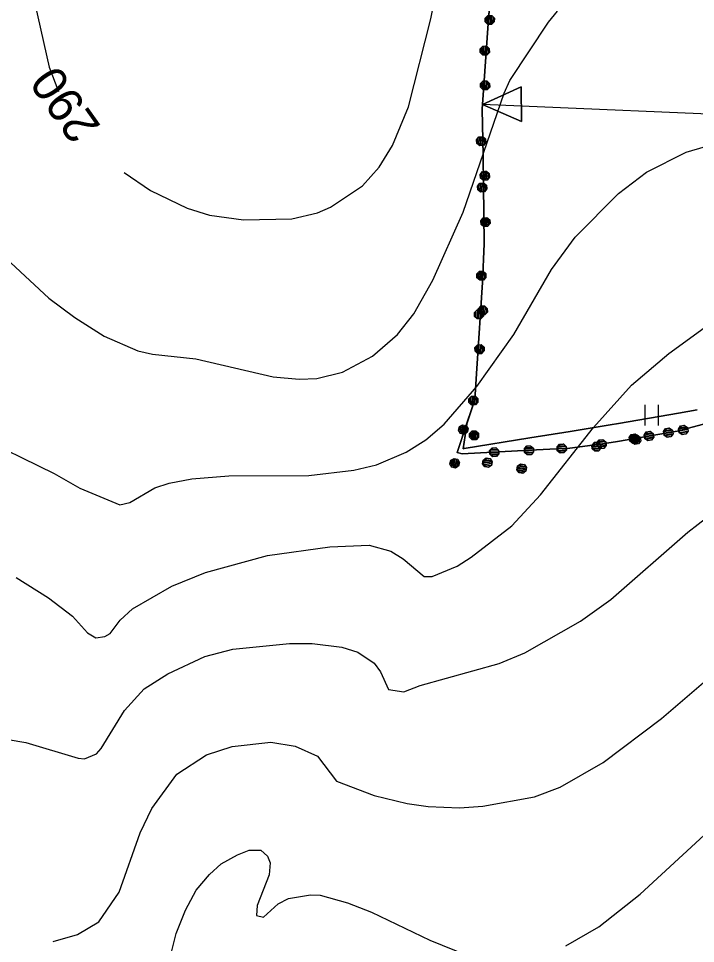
# Model space of a CAD drawing. Extents: x -645676 to -642474, y -1077513 to -1072613.
# Drawn here: x -644532.5 to -644289.3, y -1077150 to -1076817.6 of the extents above; entities that cross this region are included whole.
import ezdxf

# ---------------------------------------------------------------- set-up
doc = ezdxf.new("R2010")
doc.units = 0
for name, color, linetype in [('KULTURY_STAV', 7, 'Continuous'), ('KULTURY_ZNACKY', 7, 'Continuous'), ('OBVOD_PU', 7, 'Continuous'), ('PC_NAVRH', 7, 'Continuous'), ('PC_STAN_NAVRH', 7, 'Continuous'), ('SPRAV_HR_STAV', 7, 'Continuous'), ('VRSTEVNICE', 7, 'Continuous'), ('Vrstevnice_zd_razn_n____popis', 7, 'Continuous')]:
    doc.layers.add(name, color=color, linetype=linetype)

# ---------------------------------------------------------------- blocks, each defined once
blk = doc.blocks.new('$920')
for points in [[(0, 0), (-2.8, 1.25), (-2.8, -1.25), (0, 0)], [(-2.8, 1.25), (0, 0), (-2.8, -1.25), (-2.8, 1.25)]]:
    blk.add_lwpolyline(points)
blk = doc.blocks.new('3$0600')
for p, q in [((-0.5, 1.5), (-0.5, 0)), ((0.5, 0), (0.5, 1.5))]:
    blk.add_line(p, q)
blk = doc.blocks.new('2$0620')
for points in [[(-1.07, 0.32), (-0.88, 0.13), (-0.88, -0.14), (-1.07, -0.33), (-1.34, -0.33), (-1.53, -0.14), (-1.53, 0.13), (-1.34, 0.32), (-1.07, 0.32), (-1.08, 0.28), (-1.32, 0.28), (-1.4, 0.2), (-1, 0.2), (-0.92, 0.12), (-1.48, 0.12), (-1.48, 0.04), (-0.92, 0.04), (-0.92, -0.04), (-1.48, -0.04), (-1.48, -0.12), (-0.92, -0.12), (-1, -0.2), (-1.4, -0.2), (-1.32, -0.28), (-1.08, -0.28)], [(1.43, 0.32), (1.62, 0.13), (1.62, -0.14), (1.43, -0.33), (1.16, -0.33), (0.97, -0.14), (0.97, 0.13), (1.16, 0.32), (1.43, 0.32), (1.4, 0.28), (1.16, 0.28), (1.08, 0.2), (1.48, 0.2), (1.56, 0.12), (1, 0.12), (1, 0.04), (1.56, 0.04), (1.56, -0.04), (1, -0.04), (1, -0.12), (1.56, -0.12), (1.48, -0.2), (1.08, -0.2), (1.16, -0.28), (1.4, -0.28)]]:
    blk.add_lwpolyline(points)

msp = doc.modelspace()

# ---------------------------------------------------------------- linework, layer by layer
at = {"layer": 'KULTURY_STAV'}
for points in [[(-644288.66, -1076958.24), (-644295.31, -1076959.39), (-644316.96, -1076963.13), (-644319.94, -1076963.65), (-644334.23, -1076965.97), (-644348.8, -1076968.33), (-644372.4, -1076972.15), (-644372.68, -1076972.2), (-644371.26, -1076962.72), (-644368.51, -1076954.59), (-644367.82, -1076943.43), (-644365.77, -1076912.5), (-644365.17, -1076898.55), (-644365.58, -1076866.83), (-644365.95, -1076850.18), (-644363.62, -1076817.66), (-644361.6, -1076794.18)], [(-644286.38, -1076963.33), (-644295.83, -1076965.87), (-644317.3, -1076969.56), (-644322.69, -1076970.48), (-644334.41, -1076971.97), (-644348.77, -1076972.74), (-644373.03, -1076974.04), (-644374.92, -1076973.51), (-644371.26, -1076962.72), (-644372.68, -1076972.2), (-644372.4, -1076972.15), (-644348.8, -1076968.33), (-644334.23, -1076965.97), (-644319.94, -1076963.65), (-644316.96, -1076963.13), (-644295.31, -1076959.39), (-644288.66, -1076958.24)]]:
    msp.add_lwpolyline(points, dxfattribs=at)
at = {"layer": 'OBVOD_PU'}
msp.add_lwpolyline([(-644286.38, -1076963.33), (-644295.83, -1076965.87), (-644317.3, -1076969.56), (-644322.69, -1076970.48), (-644334.41, -1076971.97), (-644348.77, -1076972.74), (-644373.03, -1076974.04), (-644374.92, -1076973.51), (-644368.51, -1076954.59), (-644367.82, -1076943.43), (-644365.77, -1076912.5), (-644365.17, -1076898.55), (-644365.58, -1076866.83), (-644365.95, -1076850.18), (-644363.62, -1076817.66), (-644361.6, -1076794.18)], dxfattribs=at)
at = {"layer": 'PC_NAVRH'}
msp.add_lwpolyline([(-644083.37, -1076889.25), (-644089.61, -1076889.25), (-644174.13, -1076881.1), (-644241.47, -1076856.39), (-644259.29, -1076853.08), (-644365.83, -1076848.5)], dxfattribs=at)
at = {"layer": 'SPRAV_HR_STAV'}
for p, q in [((-644361.6, -1076794.18), (-644363.62, -1076817.66)), ((-644363.62, -1076817.66), (-644365.95, -1076850.18)), ((-644365.95, -1076850.18), (-644365.58, -1076866.83)), ((-644365.58, -1076866.83), (-644365.17, -1076898.55)), ((-644365.17, -1076898.55), (-644365.77, -1076912.5)), ((-644365.77, -1076912.5), (-644367.82, -1076943.43)), ((-644367.82, -1076943.43), (-644368.51, -1076954.59)), ((-644368.51, -1076954.59), (-644374.92, -1076973.51)), ((-644295.83, -1076965.87), (-644286.38, -1076963.33)), ((-644317.3, -1076969.56), (-644295.83, -1076965.87)), ((-644322.69, -1076970.48), (-644317.3, -1076969.56)), ((-644373.03, -1076974.04), (-644348.77, -1076972.74)), ((-644348.77, -1076972.74), (-644334.41, -1076971.97)), ((-644334.41, -1076971.97), (-644322.69, -1076970.48)), ((-644374.92, -1076973.51), (-644373.03, -1076974.04))]:
    msp.add_line(p, q, dxfattribs=at)
at = {"layer": 'VRSTEVNICE'}
for points in [[(-644773.46, -1076651.61), (-644761.29, -1076663.49), (-644749.13, -1076677.39), (-644734.79, -1076698.25), (-644717.55, -1076725.33), (-644704.96, -1076737.78), (-644693.95, -1076744.59), (-644683.67, -1076749.22), (-644667.45, -1076753.71), (-644647.17, -1076755.74), (-644611.84, -1076755.74), (-644603.73, -1076756.32), (-644590.69, -1076758.35), (-644582, -1076760.52), (-644569.84, -1076764.72), (-644553.62, -1076773.12), (-644545.22, -1076779.64), (-644537.25, -1076788.04), (-644533.92, -1076793.25), (-644531.31, -1076798.9), (-644526.68, -1076812.22), (-644521.47, -1076835.1), (-644518.14, -1076843.79)], [(-644383.89, -1077018.16), (-644374.91, -1077014.39), (-644369.84, -1077011.21), (-644355.21, -1076999.91), (-644344.93, -1076988.76), (-644325.96, -1076964.57), (-644312.2, -1076949.37), (-644298.88, -1076937.93), (-644282.22, -1076925.91), (-644271.51, -1076920.55), (-644264.55, -1076918.67), (-644253.84, -1076917.07), (-644235.01, -1076916.93), (-644221.4, -1076919.24), (-644213.58, -1076918.95), (-644207.64, -1076916.64), (-644204.02, -1076914.32), (-644198.23, -1076908.38), (-644185.77, -1076884.05), (-644178.53, -1076864.94), (-644169.7, -1076838.87), (-644153.77, -1076772.83)], [(-644494.53, -1076872.9), (-644485.12, -1076879.42), (-644471.94, -1076885.79), (-644463.83, -1076888.25), (-644451.66, -1076889.99), (-644434.28, -1076889.56), (-644425.02, -1076887.38), (-644420.38, -1076885.36), (-644408.94, -1076877.68), (-644402.86, -1076871.02), (-644398.08, -1076863.2), (-644392.43, -1076849.29), (-644384.32, -1076817.73), (-644378.24, -1076787.31)], [(-644354.49, -1076931.12), (-644341.02, -1076907.8), (-644332.48, -1076896.22), (-644316.98, -1076880.43), (-644306.84, -1076872.76), (-644292.65, -1076865.66), (-644285.7, -1076863.63), (-644278.75, -1076863.05), (-644272.95, -1076863.63), (-644259.05, -1076866.53), (-644228.93, -1076875.65), (-644220.24, -1076875.51), (-644214.45, -1076873.48), (-644209.38, -1076870.15), (-644204.74, -1076865.66), (-644198.37, -1076857.12), (-644190.26, -1076843.79), (-644180.56, -1076823.52), (-644173.9, -1076806.14)], [(-644468.75, -1076939.95), (-644440.95, -1076946.33), (-644431.68, -1076947.2), (-644425.31, -1076946.91), (-644416.04, -1076944.73), (-644405.32, -1076938.94), (-644396.34, -1076931.12), (-644390.4, -1076923.73), (-644383.6, -1076911.57), (-644372.74, -1076887.24), (-644357.96, -1076844.37), (-644355.94, -1076839.88), (-644342.03, -1076818.88), (-644338.85, -1076814.97)], [(-644335.81, -1077150.81), (-644323.93, -1077144.01), (-644309.16, -1077132.28), (-644286.13, -1077111.13), (-644259.92, -1077085.5), (-644234.29, -1077056.82), (-644218.07, -1077035.54), (-644187.22, -1076991.22), (-644168.54, -1076966.89), (-644160.43, -1076951.68), (-644127.41, -1076861.17), (-644124.08, -1076849.01), (-644121.76, -1076842.92), (-644117.42, -1076836.84), (-644111.91, -1076832.35), (-644109.16, -1076831.19), (-644104.09, -1076831.63), (-644098.88, -1076833.66), (-644091.93, -1076837.86)], [(-644535.23, -1076905.34), (-644521.61, -1076918.09), (-644512.2, -1076925.04), (-644501.77, -1076931.7), (-644489.61, -1076937.06), (-644484.39, -1076938.22), (-644468.75, -1076939.95)], [(-644548.69, -1076967.03), (-644519.73, -1076981.08), (-644510.46, -1076986.44), (-644496.12, -1076992.38), (-644492.5, -1076991.51), (-644483.52, -1076986.3), (-644478.31, -1076984.56), (-644470.2, -1076982.97), (-644456.88, -1076981.95), (-644428.2, -1076981.81), (-644411.98, -1076979.92), (-644403.87, -1076978.04), (-644393.16, -1076973.41), (-644386.2, -1076969.06), (-644379.54, -1076963.42), (-644367.81, -1076949.8), (-644354.49, -1076931.12)], [(-644560.28, -1077072.61), (-644529.87, -1077077.82), (-644511.04, -1077083.47), (-644508.72, -1077083.62), (-644504.52, -1077081.88), (-644502.79, -1077080), (-644494.39, -1077066.24), (-644487.29, -1077058.56), (-644478.89, -1077053.06), (-644465.57, -1077046.83), (-644455.43, -1077044.23), (-644435.15, -1077042.2), (-644427.04, -1077042.2), (-644416.33, -1077043.5), (-644410.53, -1077045.38), (-644404.74, -1077049.29), (-644402.42, -1077052.34), (-644399.53, -1077058.71), (-644394.02, -1077059.58), (-644388.23, -1077057.26), (-644359.85, -1077049.44), (-644350.58, -1077045.53), (-644330.59, -1077034.23), (-644319.73, -1077026.41), (-644292.07, -1077002.23), (-644269.77, -1076984.99)], [(-644533.34, -1077018.45), (-644521.76, -1077025.83), (-644513.07, -1077032.35), (-644507.71, -1077038.43), (-644504.67, -1077040.17), (-644501.48, -1077039.74), (-644499.6, -1077038.58), (-644495.98, -1077033.8), (-644491.49, -1077029.74), (-644477.44, -1077021.63), (-644465.28, -1077016.71), (-644442.97, -1077010.63), (-644420.67, -1077007.44), (-644406.48, -1077006.86), (-644398.66, -1077009.03), (-644394.31, -1077011.78), (-644386.78, -1077018.16), (-644383.89, -1077018.16)], [(-644520.02, -1077149.37), (-644511.33, -1077146.76), (-644503.65, -1077142.27), (-644496.27, -1077131.55), (-644488.74, -1077110.26), (-644484.54, -1077101.57), (-644475.56, -1077089.12), (-644464.99, -1077082.17), (-644455.72, -1077079.27), (-644441.82, -1077077.68), (-644433.13, -1077079.13), (-644425.02, -1077082.75), (-644418.21, -1077091.73), (-644404.74, -1077096.79), (-644392.87, -1077099.69), (-644385.34, -1077100.85), (-644374.04, -1077101.28), (-644365.64, -1077100.71), (-644347.1, -1077097.37), (-644337.83, -1077093.9), (-644322.48, -1077084.92), (-644301.48, -1077069.13), (-644284.68, -1077054.8)], [(-644480.63, -1077165.59), (-644475.85, -1077146.47), (-644472.52, -1077138.07), (-644468.61, -1077130.83), (-644463.83, -1077125.18), (-644459.63, -1077121.41), (-644453.85, -1077118.2), (-644449.64, -1077116.49), (-644445.44, -1077116.49), (-644442.97, -1077118.66), (-644442.1, -1077120.98), (-644442.39, -1077125.33), (-644446.74, -1077136.33), (-644446.96, -1077139.91), (-644444.5, -1077140.62), (-644439.21, -1077135.75), (-644435.44, -1077133.87), (-644427.62, -1077132.57), (-644424.15, -1077132.71), (-644414.3, -1077135.46), (-644405.61, -1077138.79), (-644384.76, -1077148.79), (-644370.85, -1077154.43)]]:
    msp.add_lwpolyline(points, dxfattribs=at)

# ---------------------------------------------------------------- block references
at = {"layer": 'KULTURY_ZNACKY', "xscale": 5, "yscale": 5}
msp.add_blockref('3$0600', (-644305.02, -1076963.91), dxfattribs=at)
at = {"layer": 'PC_STAN_NAVRH', "xscale": 4.999999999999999, "yscale": 5, "rotation": -179.36470300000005}
msp.add_blockref('$920', (-644365.83, -1076848.5), dxfattribs=at)
at = {"layer": 'SPRAV_HR_STAV'}
for p, xscale, yscale, rotation in [((-644363.1, -1076811.62), 4.999999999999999, 5, -90.29051000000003), ((-644364.87, -1076835.12), 4.999999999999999, 4.999999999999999, -89.45727699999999), ((-644365.56, -1076867.68), 4.999999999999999, 5, -83.99235399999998), ((-644365.35, -1076884.33), 4.999999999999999, 5.000000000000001, -84.53415700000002), ((-644365.92, -1076916.03), 5, 5, -87.793424), ((-644366.93, -1076929.96), 4.999999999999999, 4.999999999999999, -89.14575), ((-644368.9, -1076960.9), 5.000000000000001, 4.999999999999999, -88.88734299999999), ((-644374.13, -1076971.16), 5, 4.999999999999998, -104.33038000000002), ((-644305.44, -1076967.54), 5, 5, 9.855324), ((-644300.05, -1076966.6), 4.999999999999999, 5.000000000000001, 9.922225), ((-644331.3, -1076971.8), 5, 5, 3.1228970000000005), ((-644317.05, -1076969.76), 5, 4.999999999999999, 7.371777), ((-644355.56, -1076973.1), 5, 5, 3.1208610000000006), ((-644358.07, -1076978.24), 5, 5, -9.654944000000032)]:
    msp.add_blockref('2$0620', p, dxfattribs=dict(at, xscale=xscale, yscale=yscale, rotation=rotation))

# ---------------------------------------------------------------- texts
at = {"layer": 'Vrstevnice_zd_razn_n____popis'}
msp.add_text('290', height=12.5, rotation=125.306, dxfattribs=at).set_placement((-644502.64, -1076856.36))

doc.saveas('drawing.dxf')
